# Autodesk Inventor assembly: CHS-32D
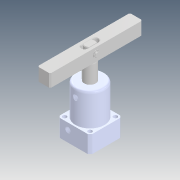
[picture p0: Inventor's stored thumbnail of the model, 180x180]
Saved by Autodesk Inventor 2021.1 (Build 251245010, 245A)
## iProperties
Created: 2020-02
Part Number: CHS-32D
Description: STEP AP214
Document SubType Name: Assembly
Designer: user
Title: chs-32d_asm1.STEP
Revision Number: ÈÎºÎ
Sending System: SolidWorks 2016
Preprocessor: SwSTEP 2.0
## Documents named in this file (6)
- D:\Vault_2016\Projekty\Clamptek\Hydraulic\CHS\CHS-32\Inventor\CHS-32D\CHS-32D.iam
- D:\Vault_2016\Projekty\Clamptek\Hydraulic\CHS\CHS-32\Inventor\CHS-32D\CHS-32-03.ipt
- D:\Vault_2016\Projekty\Clamptek\Hydraulic\CHS\CHS-32\Inventor\CHS-32D\CHS-32D-02_1.ipt
- D:\Vault_2016\Projekty\Clamptek\Hydraulic\CHS\CHS-32\Inventor\CHS-32D\CHS-32D-01.ipt
- D:\Vault_2016\Projekty\Clamptek\Hydraulic\CHS\CHS-32\Inventor\CHS-32D\Xiao.ipt
- D:\Vault_2016\Projekty\Clamptek\Hydraulic\CHS\CHS-32\Inventor\CHS-32D\Öá8µ²È¦.ipt
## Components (6 placed, 6 different names)
1. CHS-32-03_1
2. CHS-32D-02_1_2
3. CHS-32D-01_3
4. Xiao_4
5. Öá8µ²È¦_5
6. Öá8µ²È¦_6
